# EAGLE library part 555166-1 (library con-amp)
AMP connector
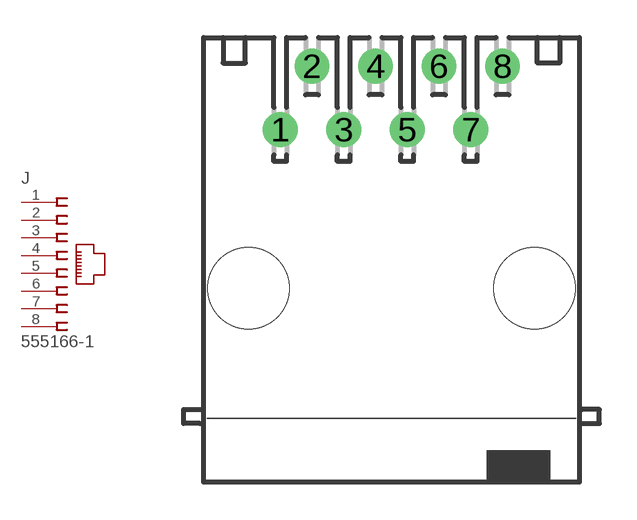
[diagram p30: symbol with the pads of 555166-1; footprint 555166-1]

Designator prefix J

## 555166-1 (MF: TYCO ELECTRONICS; MPN: 5555166-1; OC_FARNELL: 1557720; OC_NEWARK: 42K8764)  [555166-1]
1  1  pas
2  2  pas
3  3  pas
4  4  pas
5  5  pas
6  6  pas
7  7  pas
8  8  pas

## Footprint 555166-1 (pad centres in mm)
Modular Jack Keyed with Panel Stops
drill 0.889 round: 1 -4.445,5.207; 2 -3.175,7.747; 3 -1.905,5.207; 4 -0.635,7.747; 5 0.635,5.207; 6 1.905,7.747; 7 3.175,5.207; 8 4.445,7.747
hole 3.251 at -5.715,-1.143
hole 3.251 at 5.715,-1.143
